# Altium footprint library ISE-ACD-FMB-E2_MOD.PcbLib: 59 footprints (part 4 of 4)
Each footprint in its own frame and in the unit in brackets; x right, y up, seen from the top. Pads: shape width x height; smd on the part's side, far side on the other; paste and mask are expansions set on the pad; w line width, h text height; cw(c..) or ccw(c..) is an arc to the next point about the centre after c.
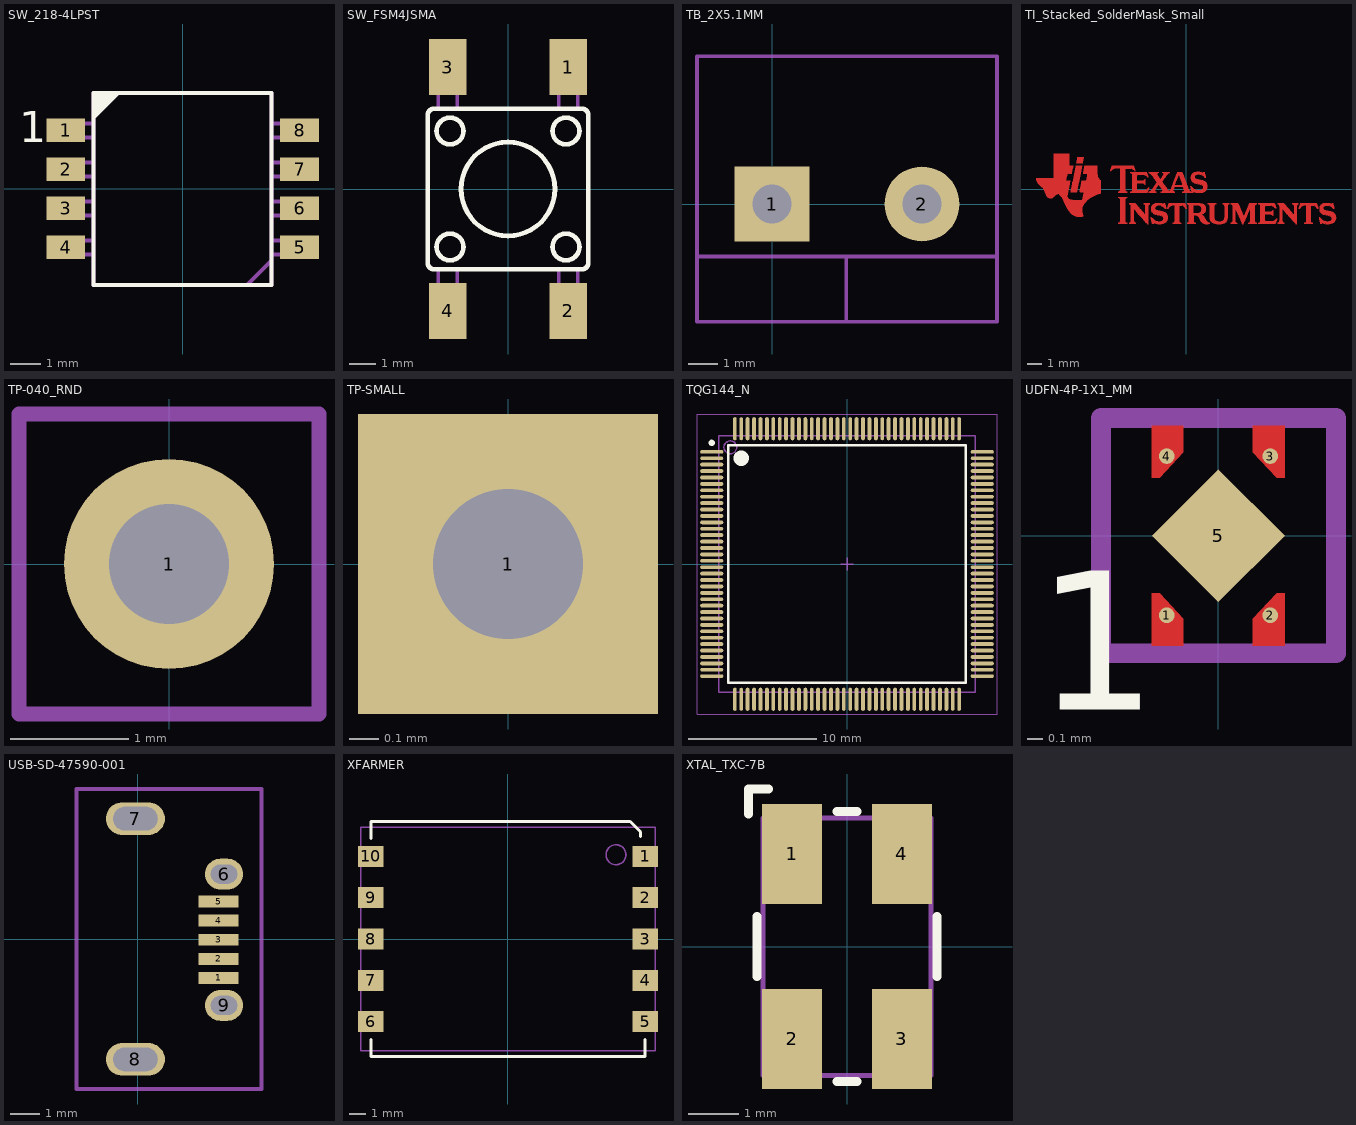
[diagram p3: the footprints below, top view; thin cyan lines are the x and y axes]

## SW_218-4LPST [mil] "CTS Components"
height 106
pads (8):
  rect 50x30 smd: 1(-150,75) 2(-150,25) 3(-150,-25) 4(-150,-75) 5(150,-75) 6(150,-25) 7(150,25) 8(150,75)
Top Overlay:
  region: -114.37,122.83 -82.87,122.83 -114.37,91.34
  lines w5: -114.37,91.34 -114.37,-123.23 82.48,-123.23 113.98,-123.23 113.98,-91.73 113.98,122.83 -82.87,122.83 ; -114.37,91.34 -82.87,122.83 ; -114.37,91.34 -114.37,122.83 -82.87,122.83
  text "1" at -210,60 h40
Mechanical 5:
  lines w5: -114.37,-84.06 -126.97,-84.06 -132.04,-84.06 -144.34,-84.06 -149.41,-84.06 -166.34,-84.06 -166.34,-66.34 -149.41,-66.34 -144.34,-66.34 -132.04,-66.34 -126.97,-66.34 -114.37,-66.34 ; -114.37,-34.06 -126.97,-34.06 -132.04,-34.06 -144.34,-34.06 -149.41,-34.06 -166.34,-34.06 -166.34,-16.34 -149.41,-16.34 -144.34,-16.34 -132.04,-16.34 -126.97,-16.34 -114.37,-16.34 ; -114.37,15.94 -126.97,15.94 -132.04,15.94 -144.34,15.94 -149.41,15.94 -166.34,15.94 -166.34,33.66 -149.41,33.66 -144.34,33.66 -132.04,33.66 -126.97,33.66 -114.37,33.66 ; -114.37,65.94 -126.97,65.94 -132.04,65.94 -144.34,65.94 -149.41,65.94 -166.34,65.94 -166.34,83.66 -149.41,83.66 -144.34,83.66 -132.04,83.66 -126.97,83.66 -114.37,83.66 ; 113.98,-84.06 126.58,-84.06 131.65,-84.06 143.94,-84.06 149.02,-84.06 165.95,-84.06 165.95,-66.34 149.02,-66.34 143.94,-66.34 131.65,-66.34 126.58,-66.34 113.98,-66.34 ; 113.98,-34.06 126.58,-34.06 131.65,-34.06 143.94,-34.06 149.02,-34.06 165.95,-34.06 165.95,-16.34 149.02,-16.34 143.94,-16.34 131.65,-16.34 126.58,-16.34 113.98,-16.34 ; 113.98,15.94 126.58,15.94 131.65,15.94 143.94,15.94 149.02,15.94 165.95,15.94 165.95,33.66 149.02,33.66 143.94,33.66 131.65,33.66 126.58,33.66 113.98,33.66 ; 113.98,65.94 126.58,65.94 131.65,65.94 143.94,65.94 149.02,65.94 165.95,65.94 165.95,83.66 149.02,83.66 143.94,83.66 131.65,83.66 126.58,83.66 113.98,83.66 ; -114.37,91.34 -114.37,122.83 -82.87,122.83 ; -114.37,91.34 -82.87,122.83 ; -114.37,91.34 -114.37,-123.23 82.48,-123.23 ; -82.87,122.83 113.98,122.83 113.98,-91.73 ; 82.48,-123.23 113.98,-91.73 ; 82.48,-123.23 113.98,-123.23 113.98,-91.73
  text "1" at -101,55 h40
  text ".Designator" at -36,-17 h36
3D body: height 103.75, standoff 0.6, extent -166.14,-123.04 166.14,123.02

## SW_FSM4JSMA [mm] "Alcoswitch"
height 5
pads (4):
  rect 1.4x2.1 smd: 1(2.25,4.55) 2(2.25,-4.55) 3(-2.25,4.55) 4(-2.25,-4.55)
Top Overlay:
  lines w0.178: -3,-2.75 ccw(c-2.75,-2.75) -2.75,-3 2.75,-3 ccw(c2.75,-2.75) 3,-2.75 3,2.75 ccw(c2.75,2.75) 2.75,3 -2.75,3 ccw(c-2.75,2.75) -3,2.75 -3,-2.75 ; -2.665,-2.165 cw(c-2.165,-2.165) -1.665,-2.165 cw(c-2.165,-2.165) -2.665,-2.165 ; -2.665,2.165 cw(c-2.165,2.165) -1.665,2.165 cw(c-2.165,2.165) -2.665,2.165 ; -1.75,0 cw(c0,0) 1.75,0 cw(c0,0) -1.75,0 ; 1.665,-2.165 ccw(c2.165,-2.165) 2.665,-2.165 ccw(c2.165,-2.165) 1.665,-2.165 ; 1.665,2.165 cw(c2.165,2.165) 2.665,2.165 cw(c2.165,2.165) 1.665,2.165
Mechanical 5:
  lines w0.127: -2.6,-3 -2.6,-3.4 -2.6,-3.95 ; -2.6,3 -2.6,3.4 -2.6,3.95 ; -1.9,-3 -1.9,-3.4 -1.9,-3.95 ; -1.9,3 -1.9,3.4 -1.9,3.95 ; 1.9,-3 1.9,-3.4 1.9,-3.95 ; 1.9,3 1.9,3.4 1.9,3.95 ; 2.6,-3 2.6,-3.4 2.6,-3.95 ; 2.6,3 2.6,3.4 2.6,3.95 ; -2.6,-3.95 -2.6,-4.2 -2.6,-5 -1.9,-5 -1.9,-4.2 -1.9,-3.95 ; -2.6,-3.95 -1.9,-3.95 ; -2.6,3.95 -2.6,4.2 -2.6,5 -1.9,5 -1.9,4.2 -1.9,3.95 ; -2.6,3.95 -1.9,3.95 ; 1.9,-3.95 1.9,-4.2 1.9,-5 2.6,-5 2.6,-4.2 2.6,-3.95 ; 1.9,-3.95 2.6,-3.95 ; 1.9,3.95 1.9,4.2 1.9,5 2.6,5 2.6,4.2 2.6,3.95 ; 1.9,3.95 2.6,3.95 ; -3,-2.75 ccw(c-2.75,-2.75) -2.75,-3 2.75,-3 ccw(c2.75,-2.75) 3,-2.75 3,2.75 ccw(c2.75,2.75) 2.75,3 -2.75,3 ccw(c-2.75,2.75) -3,2.75 -3,-2.75 ; -2.665,-2.165 ccw(c-2.165,-2.165) -1.665,-2.165 ccw(c-2.165,-2.165) -2.665,-2.165 ; -2.665,2.165 ccw(c-2.165,2.165) -1.665,2.165 ccw(c-2.165,2.165) -2.665,2.165 ; -1.75,0 ccw(c0,0) 1.75,0 ccw(c0,0) -1.75,0 ; 1.665,-2.165 cw(c2.165,-2.165) 2.665,-2.165 cw(c2.165,-2.165) 1.665,-2.165 ; 1.665,2.165 ccw(c2.165,2.165) 2.665,2.165 ccw(c2.165,2.165) 1.665,2.165
  text ".Designator" at 0.595,0.384 h0.91
3D body: height 5.1, standoff 0.02, extent -3,-5 3,5

## TB_2X5.1MM [mil]
pads (2):
  rect 100x100 hole 52: 1(0,0)
  round 100 hole 52: 2(200,0)
Mechanical 5:
  lines w5: -100,-70 300,-70 ; 99,-157 99,-70 ; -100,-157 -100,197 300,197 300,-157 -100,-157
  text ".Designator" at 69,74.1 h36

## TI_Stacked_SolderMask_Small [mm]
pads (1):
  rect 0x0 smd paste-3.175 mask-3.175: 0(0,0)
Top Layer:
  drawing of 18 lines, arcs and shapes, not listed

## TP-040_RND [mil]
pads (1):
  round 70 / inner round 62 / far side round 62 hole 40: 1(0,0)
Mechanical 5:
  lines w5: -50,-50 50,-50 50,50 -50,50 -50,-50

## TP-SMALL [mil]
pads (1):
  rect 40x40 hole 20: 1(0,0)

## TQG144_N [mm] "Thin QFP, 144-Leads, Body 20x20mm, Pitch 0.5mm, IPC Medium Density"
height 1.6
pads (144):
  oval 1.8x0.3 smd mask+0.051: 1(-10.55,8.75) 2(-10.55,8.25) 3(-10.55,7.75) 4(-10.55,7.25) 5(-10.55,6.75) 6(-10.55,6.25) 7(-10.55,5.75) 8(-10.55,5.25) 9(-10.55,4.75) 10(-10.55,4.25) 11(-10.55,3.75) 12(-10.55,3.25) 13(-10.55,2.75) 14(-10.55,2.25) 15(-10.55,1.75) 16(-10.55,1.25) 17(-10.55,0.75) 18(-10.55,0.25) 19(-10.55,-0.25) 20(-10.55,-0.75) 21(-10.55,-1.25) 22(-10.55,-1.75) 23(-10.55,-2.25) 24(-10.55,-2.75) 25(-10.55,-3.25) 26(-10.55,-3.75) 27(-10.55,-4.25) 28(-10.55,-4.75) 29(-10.55,-5.25) 30(-10.55,-5.75) 31(-10.55,-6.25) 32(-10.55,-6.75) 33(-10.55,-7.25) 34(-10.55,-7.75) 35(-10.55,-8.25) 36(-10.55,-8.75) 73(10.55,-8.75) 74(10.55,-8.25) 75(10.55,-7.75) 76(10.55,-7.25) 77(10.55,-6.75) 78(10.55,-6.25) 79(10.55,-5.75) 80(10.55,-5.25) 81(10.55,-4.75) 82(10.55,-4.25) 83(10.55,-3.75) 84(10.55,-3.25) 85(10.55,-2.75) 86(10.55,-2.25) 87(10.55,-1.75) 88(10.55,-1.25) 89(10.55,-0.75) 90(10.55,-0.25) 91(10.55,0.25) 92(10.55,0.75) 93(10.55,1.25) 94(10.55,1.75) 95(10.55,2.25) 96(10.55,2.75) 97(10.55,3.25) 98(10.55,3.75) 99(10.55,4.25) 100(10.55,4.75) 101(10.55,5.25) 102(10.55,5.75) 103(10.55,6.25) 104(10.55,6.75) 105(10.55,7.25) 106(10.55,7.75) 107(10.55,8.25) 108(10.55,8.75)
  oval 0.3x1.8 smd mask+0.051: 37(-8.75,-10.55) 38(-8.25,-10.55) 39(-7.75,-10.55) 40(-7.25,-10.55) 41(-6.75,-10.55) 42(-6.25,-10.55) 43(-5.75,-10.55) 44(-5.25,-10.55) 45(-4.75,-10.55) 46(-4.25,-10.55) 47(-3.75,-10.55) 48(-3.25,-10.55) 49(-2.75,-10.55) 50(-2.25,-10.55) 51(-1.75,-10.55) 52(-1.25,-10.55) 53(-0.75,-10.55) 54(-0.25,-10.55) 55(0.25,-10.55) 56(0.75,-10.55) 57(1.25,-10.55) 58(1.75,-10.55) 59(2.25,-10.55) 60(2.75,-10.55) 61(3.25,-10.55) 62(3.75,-10.55) 63(4.25,-10.55) 64(4.75,-10.55) 65(5.25,-10.55) 66(5.75,-10.55) 67(6.25,-10.55) 68(6.75,-10.55) 69(7.25,-10.55) 70(7.75,-10.55) 71(8.25,-10.55) 72(8.75,-10.55) 109(8.75,10.55) 110(8.25,10.55) 111(7.75,10.55) 112(7.25,10.55) 113(6.75,10.55) 114(6.25,10.55) 115(5.75,10.55) 116(5.25,10.55) 117(4.75,10.55) 118(4.25,10.55) 119(3.75,10.55) 120(3.25,10.55) 121(2.75,10.55) 122(2.25,10.55) 123(1.75,10.55) 124(1.25,10.55) 125(0.75,10.55) 126(0.25,10.55) 127(-0.25,10.55) 128(-0.75,10.55) 129(-1.25,10.55) 130(-1.75,10.55) 131(-2.25,10.55) 132(-2.75,10.55) 133(-3.25,10.55) 134(-3.75,10.55) 135(-4.25,10.55) 136(-4.75,10.55) 137(-5.25,10.55) 138(-5.75,10.55) 139(-6.25,10.55) 140(-6.75,10.55) 141(-7.25,10.55) 142(-7.75,10.55) 143(-8.25,10.55) 144(-8.75,10.55)
Top Overlay:
  circle w0.25: c-10.55,9.45 r0.125
  circle w0.6: c-8.25,8.25 r0.3
  lines w0.2: -9.25,-9.25 -9.25,9.25 9.25,9.25 9.25,-9.25 -9.25,-9.25
Mechanical 5:
  circle w0.1: c-9.1,9.1 r0.5
  lines w0.1: -10,-10 -10,10 10,10 10,-10 -10,-10
  text ".Designator" at -1.524,-0.508 h0.91
Mechanical 15:
  lines w0.05: -11.7,-11.7 -11.7,11.7 11.7,11.7 11.7,-11.7 -11.7,-11.7
  lines w0.1: -0.5,0 0.5,0 ; 0,-0.5 0,0.5
3D body: height 1.6, standoff 0, extent -10,-10 10,10
3D body: height 1.61, standoff 1, extent -9.609,8.591 -8.591,9.609

## UDFN-4P-1X1_MM [mm]
pads (5):
  round 0.1 smd mask+0: 1(-0.33,-0.508) 2(0.33,-0.508) 3(0.33,0.508) 4(-0.33,0.508)
  rrect0% 0.6x0.6 smd rot 135 mask+0: 5(0,0)
Top Layer:
  region: -0.224,-0.701 -0.427,-0.701 -0.427,-0.368 -0.376,-0.368 -0.224,-0.531
  region: 0.218,-0.701 0.422,-0.701 0.422,-0.368 0.371,-0.368 0.218,-0.531
  region: 0.218,0.701 0.422,0.701 0.422,0.368 0.371,0.368 0.218,0.531
  region: -0.224,0.701 -0.427,0.701 -0.427,0.368 -0.376,0.368 -0.224,0.531
Top Overlay:
  text "1" at -1.164,-1.111 h0.89
Top Solder:
  region: 0.438,0.701 0.433,0.713 0.422,0.717 0.422,0.716 0.218,0.717 0.207,0.713 0.202,0.701 0.203,0.701 0.202,0.531 0.207,0.52 0.208,0.521 0.359,0.357 0.371,0.352 0.371,0.353 0.422,0.352 0.433,0.357 0.438,0.368 0.437,0.368 0.437,0.701
  region: -0.207,0.701 -0.212,0.713 -0.224,0.717 -0.224,0.716 -0.427,0.717 -0.438,0.713 -0.443,0.701 -0.442,0.701 -0.443,0.368 -0.438,0.357 -0.427,0.352 -0.427,0.353 -0.376,0.352 -0.364,0.357 -0.365,0.358 -0.212,0.52 -0.207,0.531 -0.209,0.531 -0.209,0.701
  region: -0.207,-0.531 -0.212,-0.52 -0.213,-0.521 -0.364,-0.357 -0.376,-0.352 -0.376,-0.353 -0.427,-0.352 -0.438,-0.357 -0.443,-0.368 -0.442,-0.368 -0.443,-0.701 -0.438,-0.713 -0.427,-0.717 -0.427,-0.716 -0.224,-0.717 -0.212,-0.713 -0.207,-0.701 -0.209,-0.701 -0.209,-0.531
  region: 0.438,-0.368 0.433,-0.357 0.422,-0.352 0.422,-0.353 0.371,-0.352 0.359,-0.357 0.36,-0.358 0.207,-0.52 0.202,-0.531 0.203,-0.531 0.202,-0.701 0.207,-0.713 0.218,-0.717 0.218,-0.716 0.422,-0.717 0.433,-0.713 0.438,-0.701 0.437,-0.701 0.437,-0.368
  region: 0.445,0 0,0.445 -0.445,0 0,-0.445
Mechanical 5:
  lines w0.127: -0.75,-0.75 -0.75,0.75 0.75,0.75 0.75,-0.75 -0.75,-0.75
  text ".Designator" at -3.19,-0.298 h0.91

## USB-SD-47590-001 [mm]
pads (9):
  rect 1.35x0.4 smd mask+0.03: 1(2.737,-1.321) 2(2.737,-0.673) 3(2.737,-0.025) 4(2.737,0.622) 5(2.737,1.27)
  oval 1.3x1.05 hole 0.65 slot 0.9 at 0 deg: 6(2.921,2.197) 9(2.921,-2.248)
  oval 2x1.1 / inner oval 2x1.1 / far side oval 2.2x1.4 hole 0.8 slot 1.5 at 0 deg: 7(-0.08,4.075) 8(-0.08,-4.075)
Mechanical 5:
  lines w0.127: -2.075,-5.08 -2.075,5.08 4.191,5.08 4.191,-5.08 -2.075,-5.08
  text ".Designator" at -0.254,-0.406 h0.91

## XFARMER [mil]
height 500
pads (10):
  rect 61x50 smd: 1(325.5,196) 2(325.5,98) 3(325.5,0) 4(325.5,-98) 5(325.5,-196) 6(-325.5,-196) 7(-325.5,-98) 8(-325.5,0) 9(-325.5,98) 10(-325.5,196)
Top Overlay:
  lines w7.09: -325.5,-239 -325.5,-279 325.5,-279 325.5,-239 ; -325.5,239 -325.5,279 290,279 314.5,254.5 314.5,243.04
Mechanical 5:
  circle w3.94: c256.38,200 r23.62
  lines w4: -349.5,-265 349.5,-265 349.5,265 -349.5,265 -349.5,-265
  text ".Designator" at -40,-14 h36
3D body: height 177.17, standoff 0, extent -349.5,-265 349.5,265

## XTAL_TXC-7B [mm] "TXC"
height 1.05
pads (4):
  rect 1.2x2 smd: 1(-1.1,1.85) 2(-1.1,-1.85) 3(1.1,-1.85) 4(1.1,1.85)
Top Overlay:
  lines w0.18: -1.975,2.65 -1.975,3.15 -1.575,3.15 ; -1.8,-0.6 -1.8,0.6 ; -0.2,-2.7 0.2,-2.7 ; -0.2,2.7 0.2,2.7 ; 1.8,-0.6 1.8,0.6
Mechanical 5:
  circle w0.1: c-1.024,1.7 r0.224
  lines w0.1: -1.675,-2.575 -1.675,2.575 1.675,2.575 1.675,-2.575 -1.675,-2.575
  text ".Designator" at 0.521,-0.889 h0.91
3D body: height 1.05, standoff 1, extent -1.674,-2.574 1.674,2.574
3D body: height 1, standoff 0, extent -1.674,-2.574 1.674,2.574
3D body: height 1.05, standoff 1, extent -1.251,1.473 -0.796,1.927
